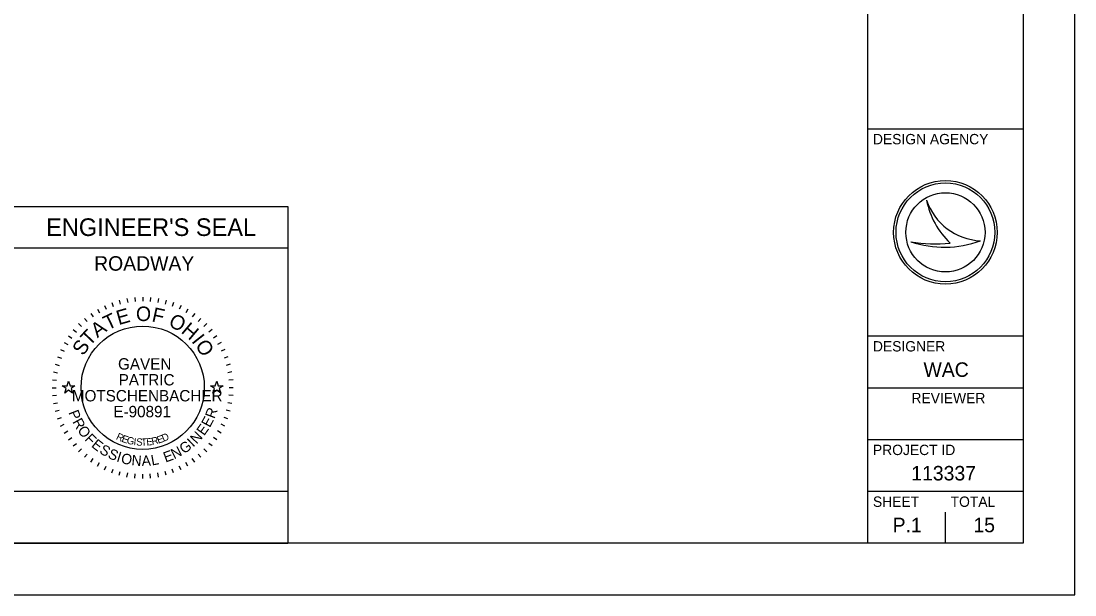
# Model space of a CAD drawing. Extents: x 0 to 34, y 0 to 22.
# Drawn here: x 23.83 to 34, y 0 to 5.54 of the extents above; entities that cross this region are included whole.
import ezdxf

# ---------------------------------------------------------------- set-up
doc = ezdxf.new("R2010")
doc.units = 0
for name, color, linetype in [('SH_Border', 7, 'Continuous'), ('SH_Cut_Line', 7, 'Continuous'), ('SH_Data', 7, 'Continuous'), ('SH_Seal', 7, 'Continuous')]:
    doc.layers.add(name, color=color, linetype=linetype)

msp = doc.modelspace()

# ---------------------------------------------------------------- linework, layer by layer
at = {"layer": 'SH_Border'}
for p, q in [((32, 0.5), (32, 21.5)), ((32, 4.5), (33.5, 4.5)), ((32, 2.5), (33.5, 2.5)), ((32, 2), (33.5, 2)), ((32, 1.5), (33.5, 1.5)), ((32, 1), (33.5, 1))]:
    msp.add_line(p, q, dxfattribs=at)
msp.add_lwpolyline([(1.5, 21.5), (33.5, 21.5), (33.5, 0.5), (1.5, 0.5)], close=True, dxfattribs=at)
at = {"layer": 'SH_Cut_Line'}
msp.add_lwpolyline([(0, 0), (34, 0), (34, 22), (0, 22)], close=True, dxfattribs=at)
at = {"layer": 'SH_Data'}
for p, q in [((32.567, 3.81), (32.567, 3.81)), ((23.6, 3.75), (26.4, 3.75)), ((26.4, 3.75), (26.4, 0.5)), ((32.75, 3.5), (32.75, 3.5)), ((32.417, 3.41), (32.417, 3.41)), ((33.087, 3.419), (33.087, 3.419)), ((23.6, 3.35), (26.4, 3.35)), ((32.75, 0.5), (32.75, 0.8)), ((32.375, 0.675), (32.375, 0.675)), ((23.6, 0.5), (26.4, 0.5))]:
    msp.add_line(p, q, dxfattribs=at)
msp.add_lwpolyline([(23.6, 0.5), (23.6, 1), (26.4, 1), (26.4, 0.5)], close=True, dxfattribs=at)
for radius in [0.5, 0.477, 0.477, 0.382]:
    msp.add_circle((32.75, 3.5), radius, dxfattribs=at)
for centre, radius, start, end in [((33.116, 3.998), 0.58, 198.9257, 198.9319), ((33.347, 3.97), 0.796, 191.6379, 191.6421), ((33.116, 3.998), 0.58, 198.9319, 267.1657), ((33.347, 3.97), 0.796, 191.6421, 226.0947), ((32.739, 4.37), 1.013, 251.4576, 290.0832), ((32.648, 4.654), 1.266, 259.4964, 259.4995), ((32.739, 4.37), 1.013, 251.4527, 251.4576), ((32.648, 4.654), 1.266, 259.4995, 276.6672)]:
    msp.add_arc(centre, radius, start, end, dxfattribs=at)
at = {"layer": 'SH_Seal'}
for p, q in [((24.848, 2.862), (24.855, 2.822)), ((24.924, 2.872), (24.927, 2.832)), ((25, 2.875), (25, 2.835)), ((25.076, 2.872), (25.073, 2.832)), ((25.152, 2.862), (25.145, 2.822)), ((24.563, 2.758), (24.583, 2.723)), ((24.63, 2.793), (24.647, 2.757)), ((24.701, 2.822), (24.714, 2.785)), ((24.774, 2.845), (24.784, 2.807)), ((25.226, 2.845), (25.216, 2.807)), ((25.299, 2.822), (25.286, 2.785)), ((25.37, 2.793), (25.353, 2.757)), ((25.437, 2.758), (25.417, 2.723)), ((24.438, 2.67), (24.463, 2.64)), ((24.498, 2.717), (24.521, 2.684)), ((25.502, 2.717), (25.479, 2.684)), ((25.562, 2.67), (25.537, 2.64)), ((24.33, 2.562), (24.36, 2.537)), ((24.381, 2.619), (24.41, 2.59)), ((25.619, 2.619), (25.59, 2.59)), ((25.67, 2.562), (25.64, 2.537)), ((24.283, 2.502), (24.316, 2.479)), ((25.717, 2.502), (25.684, 2.479)), ((24.207, 2.37), (24.243, 2.353)), ((24.242, 2.438), (24.277, 2.418)), ((25.758, 2.438), (25.723, 2.418)), ((25.793, 2.37), (25.757, 2.353)), ((24.178, 2.299), (24.215, 2.286)), ((25.822, 2.299), (25.785, 2.286)), ((24.138, 2.152), (24.178, 2.145)), ((24.155, 2.226), (24.193, 2.216)), ((25.845, 2.226), (25.807, 2.216)), ((25.862, 2.152), (25.822, 2.145)), ((24.128, 2.076), (24.168, 2.073)), ((25.872, 2.076), (25.832, 2.073)), ((24.125, 2), (24.165, 2)), ((25.875, 2), (25.835, 2)), ((24.128, 1.924), (24.168, 1.927)), ((24.138, 1.848), (24.178, 1.855)), ((25.862, 1.848), (25.822, 1.855)), ((25.872, 1.924), (25.832, 1.927)), ((24.155, 1.774), (24.193, 1.784)), ((25.845, 1.774), (25.807, 1.784)), ((24.178, 1.701), (24.215, 1.714)), ((24.207, 1.63), (24.243, 1.647)), ((25.793, 1.63), (25.757, 1.647)), ((25.822, 1.701), (25.785, 1.714)), ((24.242, 1.563), (24.277, 1.583)), ((25.758, 1.563), (25.723, 1.583)), ((24.283, 1.498), (24.316, 1.521)), ((24.33, 1.438), (24.36, 1.463)), ((25.67, 1.438), (25.64, 1.463)), ((25.717, 1.498), (25.684, 1.521)), ((24.381, 1.381), (24.41, 1.41)), ((24.438, 1.33), (24.463, 1.36)), ((25.562, 1.33), (25.537, 1.36)), ((25.619, 1.381), (25.59, 1.41)), ((24.498, 1.283), (24.521, 1.316)), ((24.563, 1.242), (24.583, 1.277)), ((24.63, 1.207), (24.647, 1.243)), ((25.37, 1.207), (25.353, 1.243)), ((25.437, 1.242), (25.417, 1.277)), ((25.502, 1.283), (25.479, 1.316)), ((24.701, 1.178), (24.714, 1.215)), ((24.774, 1.155), (24.784, 1.193)), ((24.848, 1.138), (24.855, 1.178)), ((24.924, 1.128), (24.927, 1.168)), ((25, 1.125), (25, 1.165)), ((25.076, 1.128), (25.073, 1.168)), ((25.152, 1.138), (25.145, 1.178)), ((25.226, 1.155), (25.216, 1.193)), ((25.299, 1.178), (25.286, 1.215))]:
    msp.add_line(p, q, dxfattribs=at)
for points in [[(24.224, 2.02), (24.271, 2.02), (24.285, 2.065), (24.299, 2.02), (24.346, 2.02), (24.308, 1.992), (24.323, 1.948), (24.285, 1.975), (24.247, 1.948), (24.262, 1.992)], [(25.654, 2.02), (25.701, 2.02), (25.715, 2.065), (25.729, 2.02), (25.776, 2.02), (25.738, 1.992), (25.753, 1.948), (25.715, 1.975), (25.677, 1.948), (25.692, 1.992)]]:
    msp.add_lwpolyline(points, close=True, dxfattribs=at)
msp.add_circle((25, 2), 0.595, dxfattribs=at)

# ---------------------------------------------------------------- texts
at = {"layer": 'SH_Data'}
for s, height, p in [('DESIGN AGENCY', 0.1, (32.05, 4.35)), ("ENGINEER'S SEAL", 0.17, (24.068, 3.465)), ('ROADWAY', 0.14, (24.531, 3.13)), ('DESIGNER', 0.1, (32.05, 2.35)), ('WAC', 0.14, (32.538, 2.105)), ('REVIEWER', 0.1, (32.422, 1.85)), ('PROJECT ID', 0.1, (32.05, 1.35)), ('113337', 0.14, (32.42, 1.105)), ('SHEET', 0.1, (32.05, 0.85)), ('TOTAL', 0.1, (32.8, 0.85)), ('P.1', 0.14, (32.24, 0.605)), ('15', 0.14, (33.02, 0.605))]:
    msp.add_text(s, height=height, dxfattribs=at).set_placement(p)
at = {"layer": 'SH_Seal'}
for s, height, rotation, p in [('E', 0.14, 15.7571, (24.768, 2.604)), ('O', 0.14, 359.7812, (24.935, 2.644)), ('F', 0.14, 347.4362, (25.081, 2.642)), ('T', 0.14, 25.7167, (24.662, 2.552)), ('O', 0.14, 332.2586, (25.24, 2.602)), ('T', 0.14, 46.4344, (24.488, 2.396)), ('A', 0.14, 36.4747, (24.563, 2.478)), ('H', 0.14, 319.9136, (25.363, 2.536)), ('S', 0.14, 57.1924, (24.428, 2.301)), ('I', 0.14, 308.367, (25.466, 2.448)), ('O', 0.14, 303.1491, (25.502, 2.409)), ('P', 0.1, 291.494, (24.282, 1.762)), ('R', 0.1, 69.2322, (25.692, 1.695)), ('R', 0.1, 298.7311, (24.319, 1.672)), ('E', 0.1, 54.758, (25.593, 1.531)), ('E', 0.1, 61.9951, (25.648, 1.61)), ('O', 0.1, 306.4666, (24.365, 1.588)), ('F', 0.1, 314.7068, (24.434, 1.498)), ('R', 0.07, 334.487, (24.737, 1.505)), ('E', 0.07, 341.04, (24.791, 1.48)), ('G', 0.07, 347.4752, (24.841, 1.462)), ('E', 0.07, 17.6836, (25.15, 1.46)), ('D', 0.07, 23.3052, (25.201, 1.477)), ('N', 0.1, 47.0224, (25.52, 1.451)), ('E', 0.1, 321.4393, (24.498, 1.435)), ('S', 0.1, 328.6764, (24.574, 1.375)), ('I', 0.07, 353.7858, (24.909, 1.447)), ('S', 0.07, 356.8926, (24.936, 1.443)), ('T', 0.07, 3.0061, (24.986, 1.439)), ('E', 0.07, 6.0117, (25.039, 1.441)), ('R', 0.07, 11.9184, (25.092, 1.447)), ('N', 0.1, 27.3113, (25.304, 1.308)), ('G', 0.1, 35.0469, (25.398, 1.357)), ('I', 0.1, 43.287, (25.487, 1.421)), ('S', 0.1, 335.9134, (24.656, 1.327)), ('I', 0.1, 343.1505, (24.741, 1.29)), ('O', 0.1, 346.8859, (24.784, 1.275)), ('N', 0.1, 355.1261, (24.889, 1.252)), ('A', 0.1, 2.8617, (24.992, 1.244)), ('L', 0.1, 10.0987, (25.089, 1.249)), ('E', 0.1, 20.0742, (25.221, 1.277))]:
    msp.add_text(s, height=height, rotation=rotation, dxfattribs=at).set_placement(p)
for s, p in [('GAVEN', (24.762, 2.175)), ('PATRIC', (24.768, 2.022)), ('MOTSCHENBACHER', (24.316, 1.868)), ('E-90891', (24.717, 1.715))]:
    msp.add_text(s, height=0.11, dxfattribs=at).set_placement(p)

doc.saveas('drawing.dxf')
